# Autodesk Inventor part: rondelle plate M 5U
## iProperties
Author: chr
Created: 2001-06
Part Number: rondelle plate M 5U
Material: Par défaut
Document SubType Name: Modélisation
Designer: chr
Control State: 0
Master: False
Checked Out: False
PropertySet Name: Design Tracking Control
Shininess: 21.0
PropertySet Name: _Private Model Information
Density: 0.0
Volumn: 0.0
Area: 0.0
PropertySet Name: Model Information
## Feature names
1. Extrusion1
